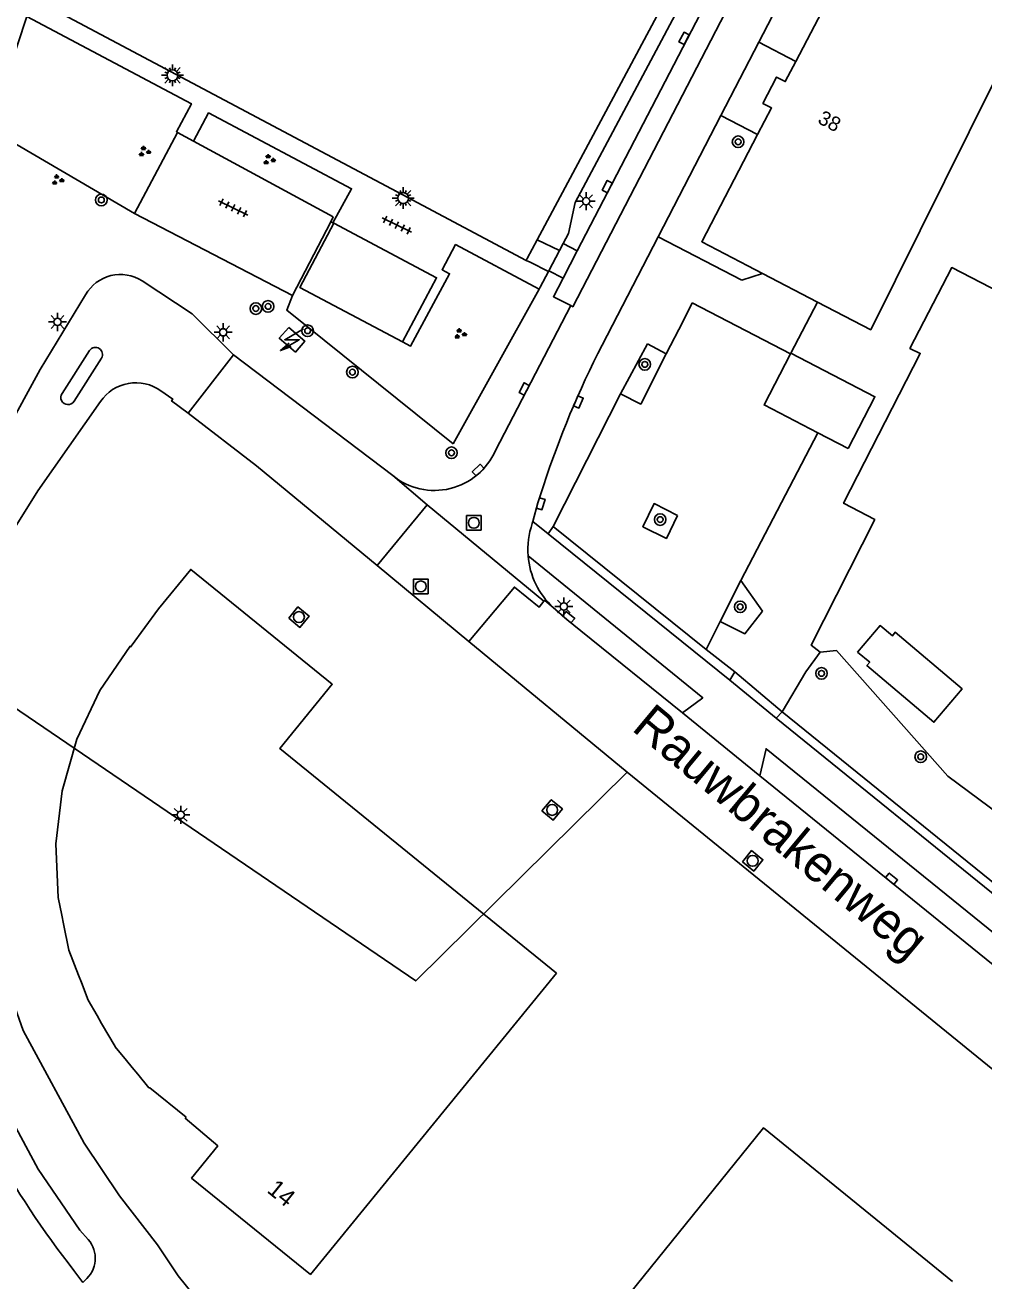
# Model space of a CAD drawing. Extents: x 136000 to 138005, y 398500 to 400500.
# Drawn here: x 137048 to 137113.9, y 399177.4 to 399263.7 of the extents above; entities that cross this region are included whole.
import ezdxf

# ---------------------------------------------------------------- set-up
doc = ezdxf.new("R2010")
doc.units = 0
for name, color, linetype in [('bs-afsc-poort', 7, 'Continuous'), ('bs-symb-veldverlichting', 7, 'Continuous'), ('gg-afsc-erfafscheiding', 7, 'Continuous'), ('gg-afsc-hekwerk', 7, 'Continuous'), ('gg-afsc-muur', 7, 'Continuous'), ('gg-anno-huisnummerreeks BGT', 7, 'Continuous'), ('gg-anno-openbare ruimte label', 7, 'Continuous'), ('gg-bbg-bijgebouw', 7, 'Continuous'), ('gg-bbg-hoofdgebouw', 7, 'Continuous'), ('gg-bbg-lage trafo', 7, 'Continuous'), ('gg-bbg-overig bouwwerk', 7, 'Continuous'), ('gg-knt-bronhoudergrens', 7, 'Continuous'), ('gg-knt-verharding', 7, 'Continuous'), ('gg-knt-verharding nz', 7, 'Continuous'), ('gt-anno-plantopografie huisnummer', 7, 'Continuous'), ('gt-bbg-plantopografie pand', 7, 'Continuous'), ('gt-grn-groengrens', 7, 'Continuous'), ('gt-grn-weggrens', 7, 'Continuous'), ('gt-symb-boom', 7, 'Continuous'), ('gt-symb-groenvak', 7, 'Continuous'), ('gt-symb-kolk', 7, 'Continuous'), ('gt-symb-lichtmast', 7, 'Continuous'), ('gt-symb-rioolschacht', 7, 'Continuous'), ('gt-symb-tegel verharding', 7, 'Continuous'), ('gt-symb-trafo symbool', 7, 'Continuous')]:
    doc.layers.add(name, color=color, linetype=linetype)

# ---------------------------------------------------------------- blocks, each defined once
blk = doc.blocks.new('gt0-BOOM')
at = {"layer": 'gt-symb-boom'}
for radius in [0.4, 0.2]:
    blk.add_circle((0, 0), radius, dxfattribs=at)
blk = doc.blocks.new('gt0-KOLK')
at = {"layer": 'gt-symb-kolk'}
blk.add_lwpolyline([(0, 0), (0.375, 0), (0.375, 0.4), (-0.375, 0.4), (-0.375, 0), (0, 0)], dxfattribs=at)
blk = doc.blocks.new('bs0-VELDV')
at = {"layer": 'bs-symb-veldverlichting'}
for p, q in [((-0.375, 0), (-0.75, 0)), ((-0.53, 0.53), (-0.265, 0.265)), ((-0.346, 0.144), (-0.52, 0.215)), ((-0.215, 0.52), (-0.144, 0.346)), ((0, 0.75), (0, 0.375)), ((0.215, 0.52), (0.144, 0.346)), ((0.265, 0.265), (0.53, 0.53)), ((0.346, 0.144), (0.52, 0.215)), ((0.375, 0), (0.75, 0)), ((-0.265, -0.265), (-0.53, -0.53)), ((-0.346, -0.144), (-0.52, -0.215)), ((-0.144, -0.346), (-0.215, -0.52)), ((0, -0.375), (0, -0.75)), ((0.144, -0.346), (0.215, -0.52)), ((0.265, -0.265), (0.53, -0.53)), ((0.346, -0.144), (0.52, -0.215))]:
    blk.add_line(p, q, dxfattribs=at)
blk.add_circle((0, 0), 0.375, dxfattribs=at)
blk = doc.blocks.new('gt0-LMAST')
at = {"layer": 'gt-symb-lichtmast'}
for p, q in [((-0.182, 0.173), (-0.447, 0.438)), ((-0.005, 0.246), (-0.005, 0.621)), ((0.172, 0.173), (0.437, 0.438)), ((-0.255, -0.004), (-0.63, -0.004)), ((-0.182, -0.181), (-0.447, -0.446)), ((-0.005, -0.254), (-0.005, -0.629)), ((0.437, -0.446), (0.172, -0.181)), ((0.245, -0.004), (0.62, -0.004))]:
    blk.add_line(p, q, dxfattribs=at)
blk.add_circle((-0.005, -0.004), 0.25, dxfattribs=at)
blk = doc.blocks.new('gt0-HSP')
at = {"layer": 'gt-symb-trafo symbool'}
for points in [[(0.771, 0.746), (-0.529, -0.004), (0.471, -0.004), (-0.829, -0.754)], [(-0.217, -0.24), (-0.829, -0.754), (-0.077, -0.48)]]:
    blk.add_lwpolyline(points, dxfattribs=at)
blk = doc.blocks.new('gt0-RS')
at = {"layer": 'gt-symb-rioolschacht'}
blk.add_lwpolyline([(-0.5, -0.5), (0.5, -0.5), (0.5, 0.5), (-0.5, 0.5)], close=True, dxfattribs=at)
blk.add_circle((0, 0), 0.375, dxfattribs=at)
blk = doc.blocks.new('gt0-GRVAK')
at = {"layer": 'gt-symb-groenvak'}
for p, q in [((-0.11, 0.189), (-0.228, 0.24)), ((-0.182, 0.153), (0.088, 0.153)), ((-0.091, 0.211), (-0.156, 0.322)), ((-0.047, 0.214), (-0.047, 0.393)), ((-0.004, 0.211), (0.061, 0.322)), ((0.015, 0.189), (0.133, 0.24)), ((0.262, -0.052), (0.197, 0.059)), ((0.305, -0.049), (0.305, 0.13)), ((0.349, -0.052), (0.414, 0.059)), ((-0.245, -0.228), (-0.363, -0.177)), ((-0.318, -0.264), (-0.047, -0.264)), ((-0.226, -0.206), (-0.291, -0.095)), ((-0.183, -0.203), (-0.183, -0.024)), ((-0.139, -0.206), (-0.074, -0.095)), ((-0.12, -0.228), (-0.002, -0.177)), ((0.243, -0.074), (0.125, -0.023)), ((0.17, -0.11), (0.441, -0.11)), ((0.368, -0.074), (0.486, -0.023))]:
    blk.add_line(p, q, dxfattribs=at)
blk = doc.blocks.new('gt0-TEG1')
at = {"layer": 'gt-symb-tegel verharding'}
for p, q in [((-1.125, 0), (1.125, 0)), ((-0.9, -0.25), (-0.9, 0.25)), ((-0.45, -0.25), (-0.45, 0.25)), ((0, -0.25), (0, 0.25)), ((0.45, -0.25), (0.45, 0.25)), ((0.9, -0.25), (0.9, 0.25))]:
    blk.add_line(p, q, dxfattribs=at)

msp = doc.modelspace()

# ---------------------------------------------------------------- linework, layer by layer
at = {"layer": 'bs-afsc-poort'}
for p, q in [((137082.762, 399247.435), (137084.017, 399246.794)), ((137096.822, 399219.26), (137100.067, 399216.519))]:
    msp.add_line(p, q, dxfattribs=at)
at = {"layer": 'gg-afsc-erfafscheiding'}
msp.add_line((137100.68, 399241.18), (137102.51, 399244.695), dxfattribs=at)
at = {"layer": 'gg-afsc-hekwerk'}
for p, q in [((137083.227, 399248.967), (137106.296, 399292.163)), ((137083.227, 399248.967), (137106.296, 399292.163)), ((137058.512, 399256.357), (137055.55, 399250.773)), ((137058.512, 399256.357), (137059.602, 399255.765)), ((137058.512, 399256.357), (137059.602, 399255.765)), ((137059.602, 399255.765), (137069.215, 399250.545)), ((137073.952, 399252.084), (137082.474, 399247.557)), ((137073.952, 399252.084), (137082.474, 399247.557)), ((137055.55, 399250.773), (137066.399, 399245.143)), ((137055.55, 399250.773), (137066.399, 399245.143)), ((137082.539, 399247.679), (137083.227, 399248.967)), ((137082.539, 399247.679), (137083.227, 399248.967)), ((137084.764, 399248.236), (137085.021, 399248.721)), ((137082.474, 399247.557), (137082.539, 399247.679)), ((137082.474, 399247.557), (137082.539, 399247.679)), ((137084.03, 399246.851), (137084.764, 399248.236)), ((137083.428, 399245.712), (137084.004, 399246.801)), ((137083.428, 399245.712), (137084.004, 399246.801)), ((137084.004, 399246.801), (137084.03, 399246.851)), ((137083.364, 399245.591), (137077.461, 399234.952)), ((137083.364, 399245.591), (137077.461, 399234.952)), ((137083.364, 399245.591), (137083.428, 399245.712)), ((137083.364, 399245.591), (137083.428, 399245.712)), ((137093.897, 399244.645), (137100.655, 399241.133)), ((137092.11, 399241.123), (137093.271, 399243.373)), ((137090.818, 399241.824), (137092.11, 399241.123)), ((137088.953, 399238.387), (137084.33, 399229.257)), ((137102.524, 399235.703), (137097.238, 399225.538)), ((137094.843, 399220.787), (137084.33, 399229.257)), ((137097.238, 399225.538), (137095.822, 399222.729)), ((137097.238, 399225.538), (137098.728, 399223.442)), ((137095.822, 399222.729), (137094.843, 399220.787)), ((137094.843, 399220.787), (137096.822, 399219.26)), ((137100.067, 399216.519), (137120.192, 399200.212))]:
    msp.add_line(p, q, dxfattribs=at)
for points in [[(137073.779, 399309.471), (137049.896, 399264.861), (137073.952, 399252.084)], [(137073.779, 399309.471), (137049.896, 399264.861), (137073.952, 399252.084)], [(137085.021, 399248.721), (137085.383, 399249.405), (137085.843, 399251.532), (137107.211, 399291.668)], [(137055.55, 399250.773), (137045.579, 399256.61), (137048.134, 399264.338)], [(137055.55, 399250.773), (137045.579, 399256.61), (137048.134, 399264.338)], [(137082.474, 399247.557), (137082.762, 399247.435), (137084.004, 399246.801)], [(137066.399, 399245.143), (137066.015, 399244.13), (137077.461, 399234.952)], [(137066.399, 399245.143), (137066.015, 399244.13), (137077.461, 399234.952)], [(137092.11, 399241.123), (137090.353, 399237.674), (137088.953, 399238.387)]]:
    msp.add_lwpolyline(points, dxfattribs=at)
at = {"layer": 'gg-afsc-muur'}
for p, q in [((137069.045, 399250.22), (137066.399, 399245.143)), ((137069.215, 399250.545), (137069.045, 399250.22))]:
    msp.add_line(p, q, dxfattribs=at)
at = {"layer": 'gg-bbg-bijgebouw'}
for p, q in [((137100.68, 399241.18), (137100.655, 399241.133)), ((137102.524, 399235.703), (137104.61, 399234.62))]:
    msp.add_line(p, q, dxfattribs=at)
for points in [[(137073.973, 399241.949), (137066.907, 399245.695), (137069.256, 399250.109)], [(137069.256, 399250.109), (137076.315, 399246.367), (137073.973, 399241.949)], [(137100.655, 399241.133), (137098.83, 399237.62), (137102.524, 399235.703)], [(137104.61, 399234.62), (137106.46, 399238.18), (137100.68, 399241.18)]]:
    msp.add_lwpolyline(points, dxfattribs=at)
at = {"layer": 'gg-bbg-hoofdgebouw'}
for p, q in [((137101.013, 399261.249), (137105.1, 399269.1)), ((137098.733, 399246.662), (137097.721, 399247.189)), ((137102.51, 399244.695), (137098.733, 399246.662))]:
    msp.add_line(p, q, dxfattribs=at)
for points in [[(137116.33, 399263.24), (137106.17, 399242.79), (137102.51, 399244.695)], [(137098.389, 399256.207), (137099.35, 399258.05), (137098.76, 399258.36), (137099.7, 399260.17), (137100.29, 399259.86), (137101.013, 399261.249)], [(137097.721, 399247.189), (137094.55, 399248.84), (137098.389, 399256.207)]]:
    msp.add_lwpolyline(points, dxfattribs=at)
at = {"layer": 'gg-bbg-lage trafo'}
msp.add_lwpolyline([(137066.148, 399242.949), (137065.496, 399242.206), (137066.604, 399241.258), (137067.247, 399242.01), (137066.148, 399242.949)], dxfattribs=at)
at = {"layer": 'gg-bbg-overig bouwwerk'}
msp.add_lwpolyline([(137105.267, 399220.607), (137106.806, 399222.445), (137107.66, 399221.732), (137107.847, 399221.98), (137112.453, 399218.083), (137110.516, 399215.793), (137105.91, 399219.689), (137106.103, 399219.918), (137105.267, 399220.607)], dxfattribs=at)
at = {"layer": 'gg-knt-bronhoudergrens'}
msp.add_lwpolyline([(137043.404, 399219.438), (137074.884, 399198), (137089.416, 399212.351)], dxfattribs=at)
at = {"layer": 'gg-knt-verharding'}
for p, q in [((137107.84, 399290.383), (137085.987, 399248.209)), ((137095.869, 399257.521), (137098.482, 399262.566)), ((137098.482, 399262.566), (137101.013, 399261.249)), ((137091.554, 399249.189), (137095.869, 399257.521)), ((137095.869, 399257.521), (137098.389, 399256.207)), ((137069.045, 399250.22), (137069.18, 399250.149)), ((137069.18, 399250.149), (137069.256, 399250.109)), ((137084.764, 399248.236), (137083.227, 399248.967)), ((137085.987, 399248.209), (137085.021, 399248.721)), ((137087.691, 399241.73), (137091.554, 399249.189)), ((137097.313, 399246.206), (137091.554, 399249.189)), ((137085.012, 399246.332), (137085.987, 399248.209)), ((137085.012, 399246.332), (137084.03, 399246.851)), ((137098.733, 399246.662), (137097.313, 399246.206)), ((137085.537, 399244.448), (137080.357, 399234.476)), ((137088.953, 399238.387), (137090.818, 399241.824)), ((137050.56, 399238.41), (137052.456, 399241.367)), ((137053.272, 399240.837), (137051.39, 399237.869)), ((137073.3, 399232.758), (137062.342, 399241.059)), ((137063.937, 399233.424), (137059.238, 399237.042)), ((137063.937, 399233.424), (137072.223, 399226.571)), ((137075.68, 399230.751), (137072.223, 399226.571)), ((137083.701, 399224.113), (137075.68, 399230.751)), ((137082.898, 399229.462), (137082.935, 399229.599)), ((137084.33, 399229.257), (137083.995, 399228.746)), ((137083.995, 399228.746), (137096.485, 399218.697)), ((137072.223, 399226.571), (137078.534, 399221.351)), ((137093.225, 399216.441), (137086.24, 399222.087)), ((137078.534, 399221.351), (137089.416, 399212.351)), ((137096.485, 399218.697), (137096.822, 399219.26)), ((137099.661, 399216.065), (137100.067, 399216.519)), ((137093.225, 399216.441), (137098.547, 399212.119)), ((137171.29, 399158.11), (137099.661, 399216.065)), ((137089.416, 399212.351), (137142.119, 399169.481)), ((137098.547, 399212.119), (137169.05, 399154.86)), ((137051.998, 399177.251), (137051.379, 399178.095)), ((137052.128, 399177.405), (137051.998, 399177.251))]:
    msp.add_line(p, q, dxfattribs=at)
for points in [[(137106.983, 399285.504), (137085.679, 399244.374), (137085.537, 399244.448)], [(137098.482, 399262.566), (137108.029, 399280.999), (137108.145, 399280.938)], [(137048.134, 399264.338), (137059.46, 399258.33), (137058.425, 399256.404), (137058.512, 399256.357)], [(137059.602, 399255.765), (137060.636, 399257.698), (137070.477, 399252.489), (137069.18, 399250.149)], [(137083.364, 399245.591), (137077.622, 399248.649), (137076.692, 399246.914), (137077.215, 399246.636), (137074.522, 399241.653), (137073.973, 399241.949)], [(137102.693, 399220.613), (137102.068, 399221.102), (137106.448, 399229.727), (137104.3, 399230.852), (137109.578, 399241.159), (137108.859, 399241.509), (137111.736, 399247.059), (137122.327, 399241.598), (137126.042, 399248.759), (137125.947, 399248.798)], [(137062.342, 399241.059), (137059.511, 399243.88), (137056.065, 399246.147)], [(137085.012, 399246.332), (137084.352, 399245.063), (137085.537, 399244.448)], [(137052.187, 399245.193), (137049.05, 399240.056), (137048.085, 399238.28), (137045.29, 399233.187), (137042.763, 399228.652), (137039.79, 399220.014), (137039.861, 399210.996), (137041.526, 399201.67), (137044.644, 399193.006), (137048.91, 399185.05), (137051.782, 399180.857), (137052.363, 399180.216)], [(137059.238, 399237.042), (137058.093, 399237.89), (137058.174, 399238.024), (137057.347, 399238.592)], [(137053.208, 399237.858), (137048.887, 399231.699), (137045.952, 399227.02), (137043.404, 399219.438)], [(137082.935, 399229.599), (137083.285, 399230.88), (137083.674, 399232.063)], [(137092.884, 399230.022), (137091.267, 399230.834), (137090.498, 399229.243), (137092.116, 399228.431), (137092.884, 399230.022)], [(137093.225, 399216.441), (137094.623, 399217.473), (137082.61, 399227.233)], [(137078.534, 399221.351), (137081.669, 399225.093), (137083.359, 399223.703), (137083.701, 399224.113)], [(137084.335, 399223.681), (137085.268, 399222.869), (137086.24, 399222.087)], [(137098.728, 399223.442), (137097.514, 399221.876), (137095.822, 399222.729)], [(137100.067, 399216.519), (137101.703, 399219.262), (137102.693, 399220.613)], [(137043.404, 399219.438), (137043.387, 399211.576), (137045.031, 399202.666), (137047.886, 399194.598), (137052.076, 399186.854), (137054.52, 399183.214), (137057.134, 399179.85), (137058.537, 399177.726), (137060.655, 399175.101), (137058.837, 399173.799), (137057.332, 399175.445)], [(137098.547, 399212.119), (137098.972, 399213.974), (137170.61, 399155.989), (137180.882, 399148.587), (137193.014, 399141.688), (137204.42, 399136.022)]]:
    msp.add_lwpolyline(points, dxfattribs=at)
for centre, radius, start, end in [((137344.063, 399161.747), 314.018, 159.01228, 161.69214), ((137054.574, 399243.848), 2.74, 57.04061, 150.6004), ((137052.857, 399241.091), 0.487, 328.51636, 145.4754), ((137145.899, 399211.874), 65.418, 152.84609, 162.02449), ((137055.637, 399236.198), 2.942, 54.46762, 145.64467), ((137050.973, 399238.136), 0.495, 146.47445, 327.33235), ((137076.177, 399236.295), 4.559, 230.87698, 336.48759), ((137088.001, 399227.67), 5.409, 160.64699, 184.62868), ((137088.023, 399227.667), 5.43, 184.58131, 227.22499), ((137100.406, 399216.664), 62.38, 208.74342, 218.19128), ((137050.891, 399178.924), 1.959, 309.16725, 41.2751)]:
    msp.add_arc(centre, radius, start, end, dxfattribs=at)
at = {"layer": 'gg-knt-verharding nz'}
for p, q in [((137062.342, 399241.059), (137059.238, 399237.042)), ((137075.68, 399230.751), (137073.3, 399232.758))]:
    msp.add_line(p, q, dxfattribs=at)
msp.add_lwpolyline([(137084.335, 399223.681), (137083.748, 399224.17), (137083.701, 399224.113)], dxfattribs=at)
at = {"layer": 'gt-bbg-plantopografie pand'}
for points in [[(137084.564, 399198.536), (137067.636, 399177.817), (137059.474, 399184.446), (137061.27, 399186.658), (137059.033, 399188.552), (137059.09, 399188.622), (137056.606, 399190.639), (137056.535, 399190.641), (137055.772, 399191.578), (137055.383, 399192.053), (137054.993, 399192.528), (137054.213, 399193.479), (137054.207, 399193.486), (137053.281, 399195.082), (137052.97, 399195.619), (137052.355, 399196.677), (137051.892, 399197.89), (137051.697, 399198.4), (137051.038, 399200.124), (137050.665, 399201.93), (137050.54, 399202.533), (137050.291, 399203.737), (137050.132, 399207.423), (137050.566, 399211.087), (137051.582, 399214.634), (137053.153, 399217.973), (137055.239, 399221.017), (137055.294, 399220.972), (137055.321, 399221.005), (137055.306, 399221.017), (137057.206, 399223.596), (137059.408, 399226.307), (137069.138, 399218.405), (137065.545, 399213.981), (137084.564, 399198.536)], [(137111.792, 399177.337), (137098.789, 399187.896), (137078.962, 399163.353), (137087.766, 399156.205), (137088.301, 399156.865), (137092.439, 399153.505)]]:
    msp.add_lwpolyline(points, dxfattribs=at)
at = {"layer": 'gt-grn-groengrens'}
msp.add_lwpolyline([(137102.693, 399220.613), (137103.804, 399220.739), (137111.466, 399212.08), (137122.926, 399203.586), (137120.192, 399200.212)], dxfattribs=at)
at = {"layer": 'gt-grn-weggrens'}
for p, q in [((137093.271, 399243.373), (137093.897, 399244.645)), ((137083.995, 399228.746), (137082.935, 399229.599)), ((137099.661, 399216.065), (137096.485, 399218.697))]:
    msp.add_line(p, q, dxfattribs=at)

# ---------------------------------------------------------------- block references
at = {"layer": 'bs-symb-veldverlichting'}
for p in [(137058.159, 399260.287), (137074.02, 399251.844)]:
    msp.add_blockref('bs0-VELDV', p, dxfattribs=at)
at = {"layer": 'gt-symb-boom'}
for p in [(137097.051, 399255.716), (137053.265, 399251.714), (137063.89, 399244.245), (137064.729, 399244.394), (137067.448, 399242.72), (137090.634, 399240.407), (137070.528, 399239.876), (137077.341, 399234.326), (137091.689, 399229.732), (137097.192, 399223.732), (137102.783, 399219.154), (137109.605, 399213.421)]:
    msp.add_blockref('gt0-BOOM', p, dxfattribs=at)
at = {"layer": 'gt-symb-groenvak'}
for p in [(137056.212, 399255.038), (137064.784, 399254.476), (137050.239, 399253.086), (137077.923, 399242.5)]:
    msp.add_blockref('gt0-GRVAK', p, dxfattribs=at)
at = {"layer": 'gt-symb-kolk'}
for p, rotation in [((137093.511, 399262.732), 62.57597352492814), ((137088.236, 399252.545), 62.62293702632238), ((137082.516, 399238.629), 62.56881089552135), ((137085.883, 399237.905), -113.18163721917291), ((137079.317, 399232.99), 43.681841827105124), ((137083.285, 399230.88), -106.76571979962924), ((137085.268, 399222.869), -39.943002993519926), ((137107.476, 399204.872), -39.321640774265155)]:
    msp.add_blockref('gt0-KOLK', p, dxfattribs=dict(at, rotation=rotation))
at = {"layer": 'gt-symb-lichtmast'}
for p in [(137086.599, 399251.631), (137050.257, 399243.328), (137061.645, 399242.615), (137085.074, 399223.758), (137058.727, 399209.428)]:
    msp.add_blockref('gt0-LMAST', p, dxfattribs=at)
at = {"layer": 'gt-symb-rioolschacht'}
for p in [(137078.878, 399229.509), (137075.234, 399225.135)]:
    msp.add_blockref('gt0-RS', p, dxfattribs=at)
for p, rotation in [((137066.849, 399223.024), -39.321640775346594), ((137084.265, 399209.763), -39.321640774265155), ((137098.049, 399206.261), -39.32164076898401)]:
    msp.add_blockref('gt0-RS', p, dxfattribs=dict(at, rotation=rotation))
at = {"layer": 'gt-symb-tegel verharding', "rotation": -26.02719868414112}
for p in [(137062.331, 399251.169), (137073.585, 399249.983)]:
    msp.add_blockref('gt0-TEG1', p, dxfattribs=at)
at = {"layer": 'gt-symb-trafo symbool'}
msp.add_blockref('gt0-HSP', (137066.405, 399242.108), dxfattribs=at)

# ---------------------------------------------------------------- texts
at = {"layer": 'gg-anno-huisnummerreeks BGT'}
msp.add_text('38', height=1, rotation=332.5, dxfattribs=at).set_placement((137102.453, 399257.039))
at = {"layer": 'gg-anno-openbare ruimte label'}
msp.add_text('Rauwbrakenweg', height=2.5, rotation=320.2, dxfattribs=at).set_placement((137089.652, 399215.294))
at = {"layer": 'gt-anno-plantopografie huisnummer'}
msp.add_text('14', height=1.2, rotation=320.9218, dxfattribs=at).set_placement((137064.588, 399183.513))

doc.saveas('drawing.dxf')
